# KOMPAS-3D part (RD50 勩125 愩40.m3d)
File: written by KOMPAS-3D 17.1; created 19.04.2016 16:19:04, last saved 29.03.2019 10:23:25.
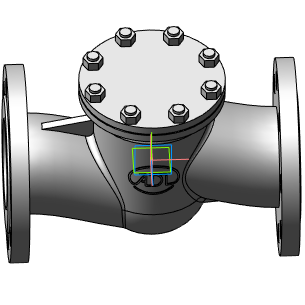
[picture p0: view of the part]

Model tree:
1. Операция без истории:2  (labels: Сталь 20  ГОСТ 1050-88)

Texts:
  RD50 Ду15 Ру40
  RD50 Ду20 Ру40
  RD50 Ду25 Ру40
  RD50 Ду32 Ру40
  RD50 Ду40 Ру40
  RD50 Ду50 Ру40
  RD50 Ду65 Ру40
  RD50 Ду80 Ру40
  RD50 Ду100 Ру40
  RD50 Ду125 Ру40
  RD50 Ду150 Ру40
  RD50 Ду200 Ру40
  RD50 Ду250 Ру40
  RD50 Ду300 Ру40
  RD50 Ду350 Ру40
  RD50 Ду400 Ру40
